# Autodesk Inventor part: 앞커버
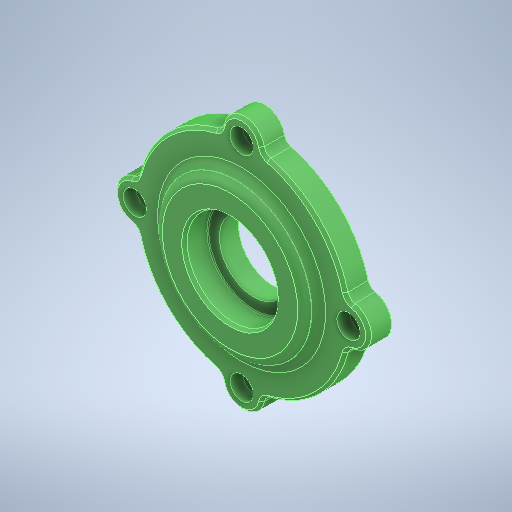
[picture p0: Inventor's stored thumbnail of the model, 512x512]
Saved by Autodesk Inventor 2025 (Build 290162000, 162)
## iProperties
Created: 2024-08
Part Number: 앞커버
Material: 알루미늄 6061
Document SubType Name: Modeling
Designer: deana
Density: 2.71 g/cm^3
Appearance: 기본값
Company: 한국ATC센터
Author: jhkim
Sending System: Autodesk Inventor 2025
Preprocessor: ST-DEVELOPER v20
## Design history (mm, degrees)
feature "솔리드1"
node "솔리드2"
